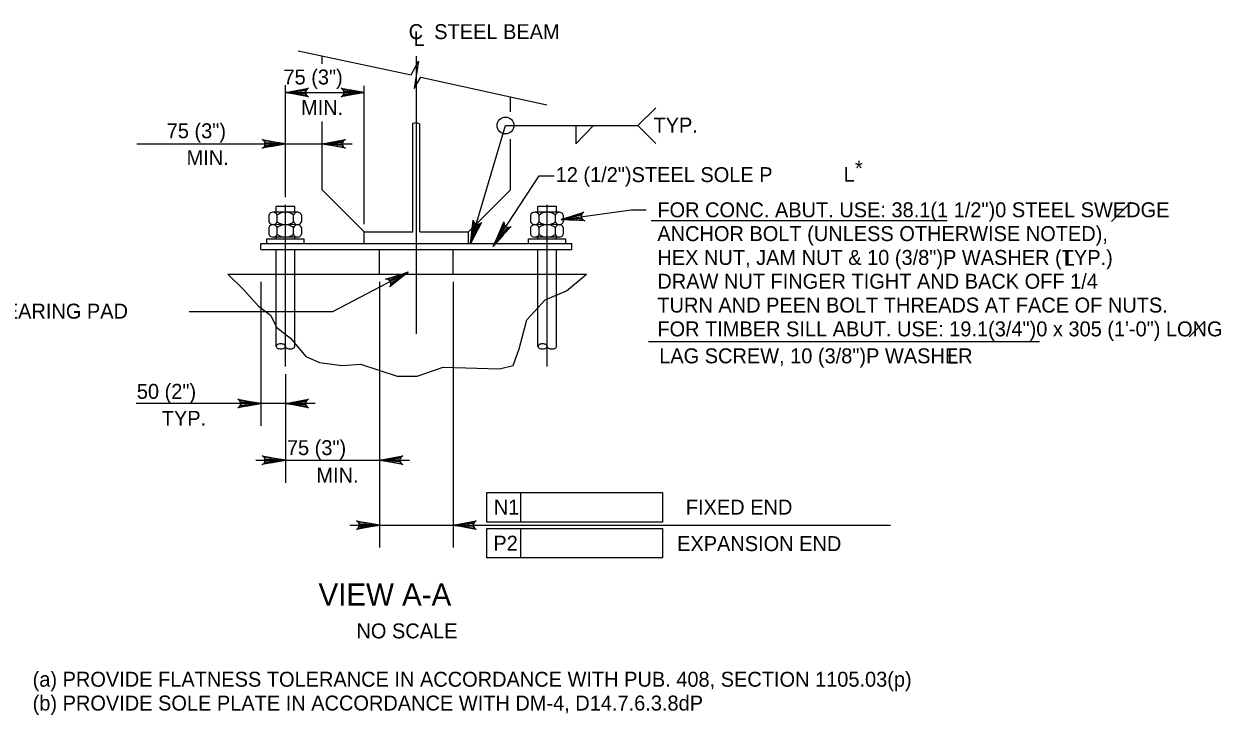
# Model space of a CAD drawing. Extents: x 638175 to 640495, y 294277 to 298435.
# Drawn here: x 638780.4 to 639020.8, y 295060.2 to 295198.9 of the extents above; entities that cross this region are included whole.
import ezdxf

# ---------------------------------------------------------------- set-up
doc = ezdxf.new("R2010")
doc.units = 0
for name, color, linetype in [('3', 7, 'Continuous'), ('4', 7, 'Continuous'), ('8', 7, 'Continuous')]:
    doc.layers.add(name, color=color, linetype=linetype)

msp = doc.modelspace()

# ---------------------------------------------------------------- linework, layer by layer
at = {"layer": '3'}
for p, q in [((638840.28, 295190.92), (638840.28, 295192.51)), ((638859.2, 295136.74), (638859.2, 295192.49)), ((638878.11, 295181.29), (638878.11, 295184.31)), ((638840.28, 295165.62), (638840.28, 295179.32)), ((638858.49, 295157.17), (638858.49, 295179.03)), ((638859.9, 295157.17), (638859.9, 295178.91)), ((638878.11, 295165.62), (638878.11, 295175.82)), ((638829.57, 295160.56), (638829.56, 295159.22)), ((638835.37, 295161.13), (638830.39, 295161.14)), ((638834.78, 295162.28), (638831.03, 295162.29)), ((638831.03, 295161.13), (638831.03, 295162.29)), ((638831.26, 295159.21), (638831.27, 295160.56)), ((638832.9, 295130.17), (638832.9, 295162.6)), ((638834.54, 295159.21), (638834.55, 295160.55)), ((638834.78, 295161.13), (638834.78, 295162.28)), ((638836.13, 295160.55), (638836.13, 295159.2)), ((638882.15, 295160.56), (638882.15, 295159.22)), ((638887.96, 295161.13), (638882.98, 295161.14)), ((638883.61, 295161.13), (638883.61, 295162.29)), ((638887.36, 295162.28), (638883.61, 295162.29)), ((638883.85, 295159.21), (638883.85, 295160.56)), ((638885.49, 295130.17), (638885.49, 295162.6)), ((638887.13, 295159.21), (638887.13, 295160.55)), ((638887.36, 295161.13), (638887.36, 295162.28)), ((638888.72, 295160.55), (638888.71, 295159.2)), ((638835.36, 295158.63), (638830.38, 295158.64)), ((638887.95, 295158.63), (638882.97, 295158.64)), ((638829.16, 295155.81), (638836.64, 295155.81)), ((638829.16, 295154.83), (638829.16, 295155.81)), ((638829.56, 295158.06), (638829.56, 295156.72)), ((638835.36, 295156.13), (638830.38, 295156.14)), ((638831.03, 295155.81), (638831.03, 295156.13)), ((638831.26, 295156.71), (638831.26, 295158.05)), ((638834.54, 295156.71), (638834.54, 295158.05)), ((638834.78, 295155.81), (638834.78, 295156.13)), ((638836.12, 295158.04), (638836.12, 295156.7)), ((638836.64, 295154.83), (638836.64, 295155.81)), ((638848.73, 295154.83), (638848.73, 295157.17)), ((638848.73, 295157.17), (638858.49, 295157.17)), ((638859.9, 295157.17), (638869.66, 295157.17)), ((638869.66, 295154.83), (638869.66, 295157.17)), ((638881.75, 295155.81), (638889.23, 295155.81)), ((638881.75, 295154.83), (638881.75, 295155.81)), ((638882.15, 295158.06), (638882.15, 295156.72)), ((638887.95, 295156.13), (638882.97, 295156.14)), ((638883.61, 295155.81), (638883.61, 295156.13)), ((638883.85, 295156.71), (638883.85, 295158.05)), ((638887.13, 295156.71), (638887.13, 295158.05)), ((638887.36, 295155.81), (638887.36, 295156.13)), ((638888.71, 295158.04), (638888.71, 295156.7)), ((638889.23, 295154.83), (638889.23, 295155.81)), ((638827.98, 295154.83), (638890.41, 295154.83)), ((638827.98, 295153.65), (638827.98, 295154.83)), ((638827.98, 295153.65), (638890.41, 295153.65)), ((638831.03, 295148.73), (638831.03, 295153.65)), ((638834.78, 295148.73), (638834.78, 295153.65)), ((638851.81, 295148.73), (638851.81, 295153.65)), ((638866.58, 295148.73), (638866.58, 295153.65)), ((638883.61, 295148.73), (638883.61, 295153.65)), ((638887.36, 295148.73), (638887.36, 295153.65)), ((638890.41, 295153.65), (638890.41, 295154.83)), ((638821.35, 295148.73), (638893.36, 295148.73)), ((638831.03, 295134.18), (638831.03, 295148.73)), ((638834.78, 295134.18), (638834.78, 295148.73)), ((638883.61, 295134.18), (638883.61, 295148.73)), ((638887.36, 295134.18), (638887.36, 295148.73))]:
    msp.add_line(p, q, dxfattribs=at)
for points in [[(638858.49, 295179.03), (638859.14, 295179.15), (638859.9, 295178.91)], [(638821.35, 295148.73), (638824.41, 295145.66), (638827.48, 295142.29), (638829.93, 295140.46), (638831.16, 295138.01), (638833.91, 295135.86), (638836.98, 295132.19), (638839.74, 295130.96), (638844.33, 295130.35), (638848.01, 295130.65), (638855.37, 295128.2), (638859.35, 295128.2), (638864.56, 295130.04), (638875.9, 295129.73), (638878.66, 295130.35), (638879.88, 295133.72), (638881.41, 295139.54), (638885.09, 295143.52), (638889.38, 295145.36), (638893.36, 295148.73)]]:
    msp.add_lwpolyline(points, dxfattribs=at)
for centre, radius, start, end in [((638830.41, 295160.23), 0.912, 88.0545, 158.5946), ((638830.41, 295160.23), 0.912, 21.1685, 88.0545), ((638832.9, 295158.52), 2.61, 50.9315, 128.8315), ((638835.34, 295160.3), 0.829, 17.3333, 162.4297), ((638883, 295160.23), 0.912, 88.0545, 158.5946), ((638883, 295160.23), 0.912, 21.1685, 88.0545), ((638885.49, 295158.52), 2.61, 50.9315, 128.8315), ((638887.92, 295160.3), 0.829, 17.3333, 162.4297), ((638830.41, 295159.55), 0.912, 201.1685, 271.7086), ((638830.41, 295157.73), 0.912, 88.0545, 158.5946), ((638830.41, 295159.55), 0.912, 271.7086, 338.5946), ((638830.41, 295157.73), 0.912, 21.1685, 88.0545), ((638832.91, 295161.24), 2.61, 230.9315, 308.8315), ((638832.9, 295156.02), 2.61, 50.9315, 128.8315), ((638835.33, 295159.46), 0.829, 197.3333, 342.4297), ((638835.33, 295157.8), 0.829, 17.3333, 162.4297), ((638883, 295159.55), 0.912, 201.1685, 271.7086), ((638883, 295157.73), 0.912, 88.0545, 158.5946), ((638883, 295159.55), 0.912, 271.7086, 338.5946), ((638883, 295157.73), 0.912, 21.1685, 88.0545), ((638885.49, 295161.24), 2.61, 230.9315, 308.8315), ((638885.48, 295156.02), 2.61, 50.9315, 128.8315), ((638887.92, 295159.46), 0.829, 197.3333, 342.4297), ((638887.92, 295157.8), 0.829, 17.3333, 162.4297), ((638830.41, 295157.05), 0.912, 201.1685, 271.7086), ((638830.41, 295157.05), 0.912, 271.7086, 338.5946), ((638832.9, 295158.74), 2.61, 230.9315, 308.8315), ((638835.33, 295156.96), 0.829, 197.3333, 342.4297), ((638883, 295157.05), 0.912, 201.1685, 271.7086), ((638883, 295157.05), 0.912, 271.7086, 338.5946), ((638885.49, 295158.74), 2.61, 230.9315, 308.8315), ((638887.92, 295156.96), 0.829, 197.3333, 342.4297), ((638831.31, 295134.2), 0.278, 142.0693, 180), ((638831.31, 295134.2), 0.278, 180, 217.9307), ((638831.62, 295133.96), 0.674, 117.9903, 142.0693), ((638831.83, 295133.57), 1.12, 102.4157, 117.9903), ((638831.97, 295132.95), 1.75, 90, 102.4157), ((638831.97, 295132.95), 1.75, 77.5843, 90), ((638832.1, 295133.57), 1.12, 62.0097, 77.5843), ((638832.31, 295133.96), 0.674, 37.9307, 62.0097), ((638832.62, 295134.2), 0.278, 0, 37.9307), ((638832.62, 295134.2), 0.278, 322.0693, 0), ((638833.18, 295134.18), 0.278, 180, 217.9307), ((638834.49, 295134.18), 0.278, 322.0693, 360), ((638834.49, 295134.18), 0.278, 360, 1.757), ((638883.9, 295134.2), 0.278, 142.0693, 180), ((638883.9, 295134.2), 0.278, 180, 217.9307), ((638884.21, 295133.96), 0.674, 117.9903, 142.0693), ((638884.42, 295133.57), 1.12, 102.4157, 117.9903), ((638884.55, 295132.95), 1.75, 90, 102.4157), ((638884.55, 295132.95), 1.75, 77.5843, 90), ((638884.69, 295133.57), 1.12, 62.0097, 77.5843), ((638884.9, 295133.96), 0.674, 37.9307, 62.0097), ((638885.21, 295134.2), 0.278, 0, 37.9307), ((638885.21, 295134.2), 0.278, 322.0693, 0), ((638885.77, 295134.18), 0.278, 180, 217.9307), ((638887.08, 295134.18), 0.278, 322.0693, 360), ((638887.08, 295134.18), 0.278, 360, 1.757), ((638831.62, 295134.45), 0.674, 217.9307, 242.0097), ((638831.83, 295134.84), 1.12, 242.0097, 257.5843), ((638831.97, 295135.46), 1.75, 257.5843, 270), ((638831.97, 295135.46), 1.75, 270, 282.4157), ((638832.1, 295134.84), 1.12, 282.4157, 297.9903), ((638832.31, 295134.45), 0.674, 297.9903, 322.0693), ((638833.49, 295134.43), 0.674, 217.9307, 242.0097), ((638833.7, 295134.82), 1.12, 242.0097, 257.5843), ((638833.84, 295135.44), 1.75, 257.5843, 270), ((638833.84, 295135.44), 1.75, 270, 282.4157), ((638833.97, 295134.82), 1.12, 282.4157, 297.9903), ((638834.18, 295134.43), 0.674, 297.9903, 322.0693), ((638884.21, 295134.45), 0.674, 217.9307, 242.0097), ((638884.42, 295134.84), 1.12, 242.0097, 257.5843), ((638884.55, 295135.46), 1.75, 257.5843, 270), ((638884.55, 295135.46), 1.75, 270, 282.4157), ((638884.69, 295134.84), 1.12, 282.4157, 297.9903), ((638884.9, 295134.45), 0.674, 297.9903, 322.0693), ((638886.08, 295134.43), 0.674, 217.9307, 242.0097), ((638886.29, 295134.82), 1.12, 242.0097, 257.5843), ((638886.42, 295135.44), 1.75, 257.5843, 270), ((638886.42, 295135.44), 1.75, 270, 282.4157), ((638886.56, 295134.82), 1.12, 282.4157, 297.9903), ((638886.77, 295134.43), 0.674, 297.9903, 322.0693)]:
    msp.add_arc(centre, radius, start, end, dxfattribs=at)
at = {"layer": '4'}
for p, q in [((638835.44, 295193.54), (638858.13, 295188.71)), ((638858.13, 295188.71), (638859.63, 295191.46)), ((638859.63, 295191.46), (638858.76, 295186)), ((638858.76, 295186), (638860.13, 295188.27)), ((638860.13, 295188.27), (638885.44, 295182.69)), ((638832.9, 295164.17), (638832.9, 295186.63)), ((638832.9, 295185.17), (638848.73, 295185.17)), ((638848.73, 295158.74), (638848.73, 295186.5)), ((638903.69, 295178.54), (638907.31, 295182.11)), ((638870.11, 295154.83), (638877.12, 295178.54)), ((638877.12, 295178.54), (638903.69, 295178.54)), ((638891.22, 295174.87), (638894.76, 295178.54)), ((638891.22, 295178.54), (638891.22, 295174.87)), ((638903.69, 295178.54), (638907.31, 295174.96)), ((638803.08, 295174.84), (638846.28, 295174.84)), ((638874.97, 295154.83), (638883.9, 295168.44)), ((638883.9, 295168.44), (638886.9, 295168.44)), ((638998.86, 295159.29), (639002.7, 295163.13)), ((638888.31, 295159.65), (638902.36, 295161.62)), ((638902.36, 295161.62), (638905.36, 295161.62)), ((638906.37, 295159.47), (638965.85, 295159.47)), ((638857.56, 295149.13), (638842.36, 295141.13)), ((638827.98, 295147.16), (638827.98, 295118.24)), ((638851.81, 295147.16), (638851.81, 295093.85)), ((638866.58, 295147.16), (638866.58, 295093.85)), ((638842.36, 295141.13), (638813.6, 295141.13)), ((639014.45, 295136.14), (639017.5, 295139.19)), ((638905.84, 295135.17), (638984.39, 295135.17)), ((638832.9, 295128.61), (638832.9, 295106.84)), ((638838.87, 295122.74), (638802.92, 295122.74)), ((638826.93, 295111.34), (638857.81, 295111.34)), ((638873.33, 295104.87), (638908.63, 295104.87)), ((638873.33, 295098.96), (638873.33, 295104.87)), ((638880.22, 295098.96), (638880.22, 295104.87)), ((638908.63, 295104.87), (638908.63, 295098.96)), ((638845.85, 295098.35), (638954.44, 295098.35)), ((638908.63, 295098.96), (638873.33, 295098.96)), ((638873.33, 295097.68), (638908.63, 295097.68)), ((638873.33, 295091.78), (638873.33, 295097.68)), ((638880.22, 295091.78), (638880.22, 295097.68)), ((638908.63, 295097.68), (638908.63, 295091.78)), ((638908.63, 295091.78), (638873.33, 295091.78))]:
    msp.add_line(p, q, dxfattribs=at)
for points in [[(638832.9, 295185.17), (638837.56, 295186.04), (638837.2, 295185.79), (638837.02, 295185.48), (638836.96, 295185.17), (638837.02, 295184.86), (638837.2, 295184.54), (638837.56, 295184.3), (638832.9, 295185.17), (638837.2, 295184.54), (638837.02, 295184.86), (638832.9, 295185.17), (638836.96, 295185.17), (638837.02, 295185.48), (638832.9, 295185.17), (638837.2, 295185.79)], [(638848.73, 295185.17), (638844.07, 295184.3), (638844.42, 295184.54), (638844.61, 295184.86), (638844.66, 295185.17), (638844.61, 295185.48), (638844.42, 295185.79), (638844.07, 295186.04), (638848.73, 295185.17), (638844.42, 295185.79), (638844.61, 295185.48), (638848.73, 295185.17), (638844.66, 295185.17), (638844.61, 295184.86), (638848.73, 295185.17), (638844.42, 295184.54)], [(638832.9, 295174.84), (638828.24, 295173.96), (638828.6, 295174.21), (638828.78, 295174.52), (638828.84, 295174.84), (638828.78, 295175.15), (638828.6, 295175.46), (638828.24, 295175.71), (638832.9, 295174.84), (638828.6, 295175.46), (638828.78, 295175.15), (638832.9, 295174.84), (638828.84, 295174.84), (638828.78, 295174.52), (638832.9, 295174.84), (638828.6, 295174.21)], [(638840.28, 295174.84), (638844.95, 295175.71), (638844.59, 295175.46), (638844.4, 295175.15), (638844.35, 295174.84), (638844.4, 295174.52), (638844.59, 295174.21), (638844.95, 295173.96), (638840.28, 295174.84), (638844.59, 295174.21), (638844.4, 295174.52), (638840.28, 295174.84), (638844.35, 295174.84), (638844.4, 295175.15), (638840.28, 295174.84), (638844.59, 295175.46)], [(638888.31, 295159.65), (638892.81, 295161.16), (638892.48, 295160.87), (638892.35, 295160.53), (638892.33, 295160.22), (638892.43, 295159.91), (638892.66, 295159.63), (638893.05, 295159.43), (638888.31, 295159.65), (638892.66, 295159.63), (638892.43, 295159.91), (638888.31, 295159.65), (638892.33, 295160.22), (638892.35, 295160.53), (638888.31, 295159.65), (638892.48, 295160.87)], [(638870.11, 295154.83), (638870.59, 295159.55), (638870.73, 295159.13), (638870.97, 295158.87), (638871.26, 295158.73), (638871.57, 295158.69), (638871.93, 295158.78), (638872.27, 295159.05), (638870.11, 295154.83), (638871.93, 295158.78), (638871.57, 295158.69), (638870.11, 295154.83), (638871.26, 295158.73), (638870.97, 295158.87), (638870.11, 295154.83), (638870.73, 295159.13)], [(638874.97, 295154.83), (638876.8, 295159.21), (638876.81, 295158.77), (638876.97, 295158.44), (638877.2, 295158.23), (638877.49, 295158.1), (638877.85, 295158.08), (638878.26, 295158.25), (638874.97, 295154.83), (638877.85, 295158.08), (638877.49, 295158.1), (638874.97, 295154.83), (638877.2, 295158.23), (638876.97, 295158.44), (638874.97, 295154.83), (638876.81, 295158.77)], [(638857.56, 295149.13), (638853.85, 295146.18), (638854.05, 295146.57), (638854.07, 295146.93), (638853.97, 295147.23), (638853.78, 295147.49), (638853.47, 295147.68), (638853.03, 295147.73), (638857.56, 295149.13), (638853.47, 295147.68), (638853.78, 295147.49), (638857.56, 295149.13), (638853.97, 295147.23), (638854.07, 295146.93), (638857.56, 295149.13), (638854.05, 295146.57)], [(638827.98, 295122.74), (638823.32, 295121.87), (638823.68, 295122.12), (638823.86, 295122.43), (638823.92, 295122.74), (638823.86, 295123.06), (638823.68, 295123.37), (638823.32, 295123.62), (638827.98, 295122.74), (638823.68, 295123.37), (638823.86, 295123.06), (638827.98, 295122.74), (638823.92, 295122.74), (638823.86, 295122.43), (638827.98, 295122.74), (638823.68, 295122.12)], [(638832.9, 295122.74), (638837.56, 295123.62), (638837.2, 295123.37), (638837.02, 295123.06), (638836.96, 295122.74), (638837.02, 295122.43), (638837.2, 295122.12), (638837.56, 295121.87), (638832.9, 295122.74), (638837.2, 295122.12), (638837.02, 295122.43), (638832.9, 295122.74), (638836.96, 295122.74), (638837.02, 295123.06), (638832.9, 295122.74), (638837.2, 295123.37)], [(638832.9, 295111.34), (638828.24, 295110.47), (638828.6, 295110.71), (638828.78, 295111.03), (638828.84, 295111.34), (638828.78, 295111.65), (638828.6, 295111.96), (638828.24, 295112.21), (638832.9, 295111.34), (638828.6, 295111.96), (638828.78, 295111.65), (638832.9, 295111.34), (638828.84, 295111.34), (638828.78, 295111.03), (638832.9, 295111.34), (638828.6, 295110.71)], [(638851.81, 295111.34), (638856.47, 295112.21), (638856.12, 295111.96), (638855.93, 295111.65), (638855.88, 295111.34), (638855.93, 295111.03), (638856.12, 295110.71), (638856.47, 295110.47), (638851.81, 295111.34), (638856.12, 295110.71), (638855.93, 295111.03), (638851.81, 295111.34), (638855.88, 295111.34), (638855.93, 295111.65), (638851.81, 295111.34), (638856.12, 295111.96)], [(638851.81, 295098.35), (638847.15, 295097.48), (638847.51, 295097.73), (638847.7, 295098.04), (638847.75, 295098.35), (638847.7, 295098.66), (638847.51, 295098.98), (638847.15, 295099.22), (638851.81, 295098.35), (638847.51, 295098.98), (638847.7, 295098.66), (638851.81, 295098.35), (638847.75, 295098.35), (638847.7, 295098.04), (638851.81, 295098.35), (638847.51, 295097.73)], [(638866.58, 295098.35), (638871.24, 295099.22), (638870.88, 295098.98), (638870.69, 295098.66), (638870.64, 295098.35), (638870.69, 295098.04), (638870.88, 295097.73), (638871.24, 295097.48), (638866.58, 295098.35), (638870.88, 295097.73), (638870.69, 295098.04), (638866.58, 295098.35), (638870.64, 295098.35), (638870.69, 295098.66), (638866.58, 295098.35), (638870.88, 295098.98)]]:
    msp.add_lwpolyline(points, dxfattribs=at)
for points in [[(638835.9, 295185.67), (638835.9, 295184.67), (638832.9, 295185.17)], [(638845.73, 295185.67), (638845.73, 295184.67), (638848.73, 295185.17)], [(638829.9, 295175.34), (638829.9, 295174.34), (638832.9, 295174.84)], [(638843.28, 295175.34), (638843.28, 295174.34), (638840.28, 295174.84)], [(638891.36, 295159.57), (638891.23, 295160.56), (638888.32, 295159.65)], [(638871.44, 295157.58), (638870.49, 295157.88), (638870.04, 295154.88)], [(638875.87, 295157.05), (638876.71, 295156.51), (638874.65, 295154.27)], [(638824.98, 295123.24), (638824.98, 295122.24), (638827.98, 295122.74)], [(638835.9, 295123.24), (638835.9, 295122.24), (638832.9, 295122.74)], [(638829.9, 295111.84), (638829.9, 295110.84), (638832.9, 295111.34)], [(638854.81, 295111.84), (638854.81, 295110.84), (638851.81, 295111.34)], [(638848.81, 295098.85), (638848.81, 295097.85), (638851.81, 295098.35)], [(638869.58, 295098.85), (638869.58, 295097.85), (638866.58, 295098.35)]]:
    msp.add_lwpolyline(points, close=True, dxfattribs=at)
msp.add_circle((638877.12, 295178.54), 1.69, dxfattribs=at)
for centre in [(638833.18, 295134.2), (638885.77, 295134.2)]:
    msp.add_arc(centre, 0.278, 180, 182.0078, dxfattribs=at)
at = {"layer": '8'}
for p, q in [((638848.73, 295157.17), (638840.28, 295165.62)), ((638869.66, 295157.17), (638878.11, 295165.62))]:
    msp.add_line(p, q, dxfattribs=at)

# ---------------------------------------------------------------- texts
at = {"layer": '4'}
for s, height, p in [('C  STEEL BEAM', 3, (638857.66, 295195.88)), ('L', 3, (638858.65, 295194.47)), ('75 (3")', 3, (638832.51, 295186.78)), ('MIN.', 3, (638836.04, 295180.67)), ('TYP.', 3, (638906.83, 295177.13)), ('75 (3")', 3, (638809.06, 295175.98)), ('MIN.', 3, (638813.04, 295170.59)), ('12 (1/2")STEEL SOLE P', 3, (638887.18, 295167.18)), ('L', 3, (638945.03, 295167.24)), ('*', 3, (638947.31, 295168.46)), ('FOR CONC. ABUT. USE: 38.1(1 1/2")0 STEEL SWEDGE', 3, (638907.61, 295160.12)), ('ANCHOR BOLT (UNLESS OTHERWISE NOTED), ', 3, (638907.61, 295155.34)), ('HEX NUT, JAM NUT & 10 (3/8")P WASHER (TYP.)', 3, (638907.61, 295150.56)), ('L', 3, (638989.22, 295150.39)), ('DRAW NUT FINGER TIGHT AND BACK OFF 1/4', 3, (638907.61, 295145.78)), ('TURN AND PEEN BOLT THREADS AT FACE OF NUTS.', 3, (638907.61, 295141)), ('ELASTOMERIC BEARING PAD', 3, (638743.99, 295139.78)), ('FOR TIMBER SILL ABUT. USE: 19.1(3/4")0 x 305 (1\'-0") LONG ', 3, (638907.61, 295136.22)), ('LAG SCREW, 10 (3/8")P WASHER', 3, (638907.98, 295130.81)), ('L', 3, (638965.84, 295130.77)), ('50 (2")', 3, (638803.06, 295123.68)), ('TYP.', 3, (638808.06, 295118.27)), ('75 (3")', 3, (638833.2, 295112.38)), ('MIN.', 3, (638839.13, 295106.84)), ('N1', 3, (638874.76, 295100.46)), ('FIXED END', 3, (638913.33, 295100.45)), ('P2', 3, (638874.67, 295093.21)), ('EXPANSION END', 3, (638911.57, 295093.12)), ('VIEW A-A', 4.429, (638839.55, 295082.19)), ('NO SCALE', 3, (638847.17, 295075.6)), ('(a) PROVIDE FLATNESS TOLERANCE IN ACCORDANCE WITH PUB. 408, SECTION 1105.03(p)', 3, (638782.13, 295065.9)), ('(b) PROVIDE SOLE PLATE IN ACCORDANCE WITH DM-4, D14.7.6.3.8dP', 3, (638782.13, 295061.12))]:
    msp.add_text(s, height=height, dxfattribs=at).set_placement(p)

doc.saveas('drawing.dxf')
